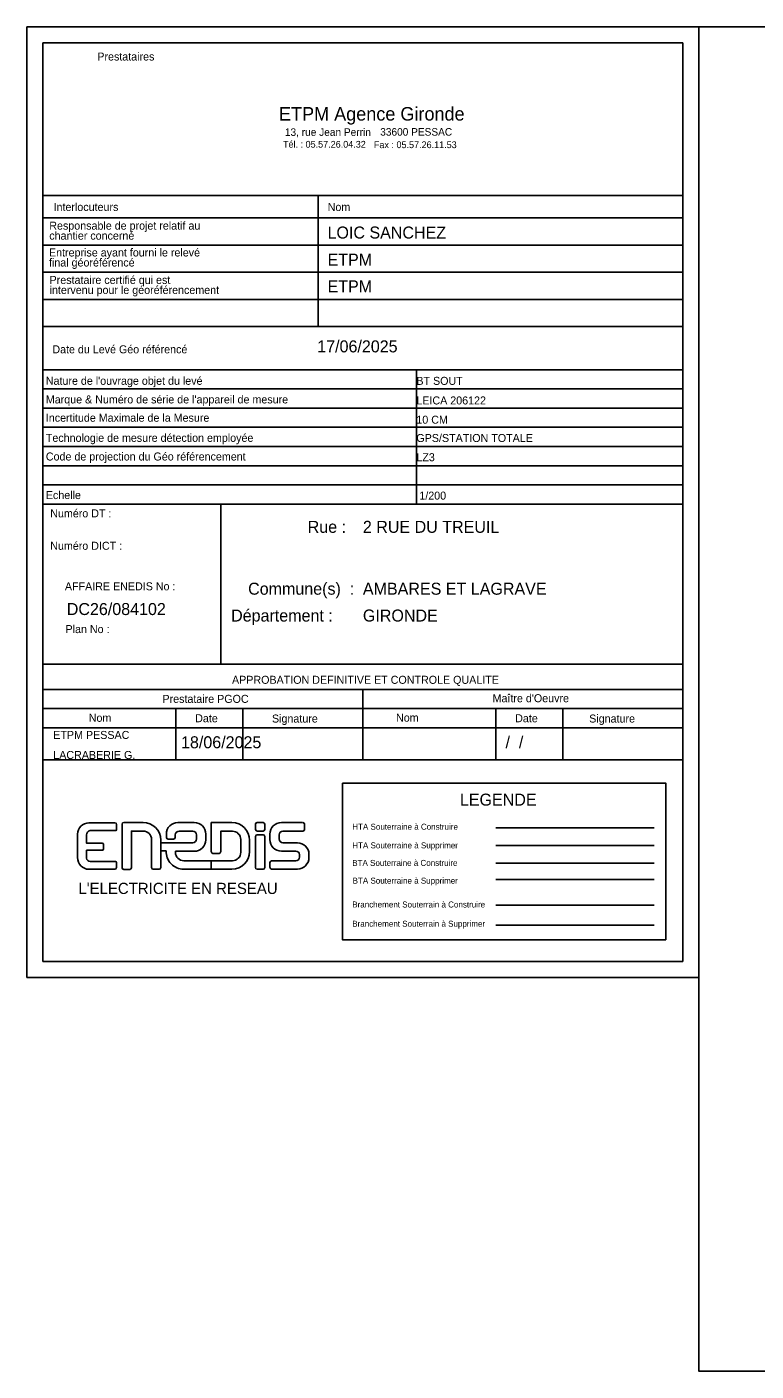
# Model space of a CAD drawing. Extents: x 376946 to 377047, y 296637 to 296721.
# Drawn here: x 376945.7 to 376991.3, y 296637.1 to 296721.1 of the extents above; entities that cross this region are included whole.
import ezdxf

# ---------------------------------------------------------------- set-up
doc = ezdxf.new("R2010")
doc.units = 0
for name, color, linetype in [('Cartouche', 7, 'Continuous'), ('CellulesEchanges', 7, 'Continuous'), ('Limites et Hydro', 7, 'Continuous'), ('PGOC_HABILLAGE_PGOC', 7, 'Continuous'), ('Texte libre', 7, 'Continuous')]:
    doc.layers.add(name, color=color, linetype=linetype)

msp = doc.modelspace()

# ---------------------------------------------------------------- linework, layer by layer
at = {"layer": 'Limites et Hydro'}
for p, q in [((376949.572, 296671.373), (376951.196, 296671.374)), ((376951.301, 296671.269), (376951.301, 296670.953)), ((376951.637, 296668.561), (376951.636, 296671.29)), ((376951.741, 296671.395), (376952.952, 296671.395)), ((376955.126, 296671.387), (376956.154, 296671.387)), ((376959.98, 296670.963), (376959.979, 296671.28)), ((376960.084, 296671.385), (376960.451, 296671.385)), ((376960.556, 296671.28), (376960.555, 296670.963)), ((376961.6, 296671.388), (376962.921, 296671.388)), ((376963.043, 296671.283), (376963.042, 296670.961)), ((376948.858, 296669.196), (376948.855, 296670.655)), ((376951.213, 296670.885), (376949.646, 296670.885)), ((376954.407, 296670.462), (376954.409, 296670.67)), ((376954.967, 296670.619), (376954.967, 296670.462)), ((376956.054, 296670.856), (376955.211, 296670.856)), ((376956.299, 296670.37), (376956.299, 296670.611)), ((376956.872, 296670.67), (376956.869, 296670.313)), ((376959.979, 296668.57), (376959.98, 296670.52)), ((376960.45, 296670.858), (376960.085, 296670.858)), ((376960.085, 296670.625), (376960.448, 296670.625)), ((376960.553, 296670.52), (376960.553, 296668.57)), ((376960.881, 296670.323), (376960.882, 296670.67)), ((376961.452, 296670.611), (376961.451, 296670.366)), ((376962.937, 296670.856), (376961.697, 296670.856)), ((376950.479, 296670.024), (376950.477, 296669.728)), ((376953.481, 296668.569), (376953.479, 296670.327)), ((376954.055, 296670.292), (376954.053, 296668.569)), ((376954.862, 296670.357), (376954.512, 296670.357)), ((376959.059, 296670.32), (376959.059, 296669.526)), ((376959.61, 296669.579), (376959.611, 296670.282)), ((376962.492, 296669.605), (376961.599, 296669.605)), ((376961.696, 296670.121), (376962.601, 296670.121)), ((376949.65, 296668.951), (376951.161, 296668.95)), ((376951.161, 296668.95), (376951.245, 296668.952)), ((376951.291, 296668.9), (376951.288, 296668.572)), ((376957.321, 296669.463), (376957.699, 296669.463)), ((376960.882, 296668.594), (376960.882, 296668.884)), ((376960.987, 296668.989), (376962.492, 296668.989)), ((376962.737, 296669.234), (376962.736, 296669.382)), ((376963.318, 296669.404), (376963.318, 296669.199)), ((376951.183, 296668.467), (376949.562, 296668.467)), ((376952.118, 296668.456), (376951.742, 296668.456)), ((376953.948, 296668.464), (376953.586, 296668.464)), ((376960.448, 296668.465), (376960.084, 296668.465)), ((376962.601, 296668.482), (376960.986, 296668.482))]:
    msp.add_line(p, q, dxfattribs=at)
for points in [[(376958.508, 296671.384), (376957.216, 296671.384), (376957.216, 296669.568)], [(376949.415, 296670.613), (376949.413, 296670.108), (376950.388, 296670.109)], [(376952.954, 296670.852), (376952.222, 296670.852), (376952.223, 296668.561)], [(376957.804, 296669.568), (376957.804, 296670.845), (376958.534, 296670.845)], [(376950.372, 296669.659), (376949.42, 296669.659), (376949.42, 296669.166)], [(376954.393, 296669.61), (376954.053, 296669.61), (376954.053, 296670.125), (376956.054, 296670.125)], [(376956.143, 296669.596), (376954.979, 296669.596), (376954.978, 296669.526)], [(376955.503, 296669.001), (376957.215, 296669.001), (376957.215, 296668.476), (376955.495, 296668.476)], [(376958.534, 296669.001), (376957.215, 296669.001), (376957.215, 296668.476), (376958.507, 296668.476)]]:
    msp.add_lwpolyline(points, dxfattribs=at)
for centre, radius, start, end in [((376949.572, 296670.655), 0.718, 90, 180), ((376951.196, 296671.269), 0.105, 0, 90), ((376951.741, 296671.29), 0.105, 90, 180), ((376952.952, 296670.292), 1.103, 0, 90), ((376955.126, 296670.67), 0.718, 90, 180), ((376956.154, 296670.67), 0.718, 0, 90), ((376958.508, 296670.282), 1.103, 0, 90), ((376960.084, 296671.28), 0.105, 90, 180), ((376960.451, 296671.28), 0.105, 0, 90), ((376961.6, 296670.67), 0.718, 90, 180), ((376962.938, 296671.283), 0.105, 0, 90), ((376949.666, 296670.633), 0.252, 94.58556, 184.58556), ((376951.223, 296670.962), 0.0783, 262.85047, 352.85047), ((376952.954, 296670.327), 0.525, 0, 90), ((376954.512, 296670.462), 0.105, 180, 270), ((376954.862, 296670.462), 0.105, 270, 0), ((376955.211, 296670.611), 0.245, 90, 178.0977), ((376956.054, 296670.611), 0.245, 0, 90), ((376956.054, 296670.37), 0.245, 270, 0), ((376958.534, 296670.32), 0.525, 0, 90), ((376960.085, 296670.963), 0.105, 180, 270), ((376960.085, 296670.52), 0.105, 90, 180), ((376960.448, 296670.52), 0.105, 0, 90), ((376960.45, 296670.963), 0.105, 270, 0), ((376961.696, 296670.366), 0.245, 180, 270), ((376961.697, 296670.611), 0.245, 90, 180), ((376962.937, 296670.961), 0.105, 270, 0), ((376950.39, 296669.746), 0.0886, 258.1056, 348.1056), ((376950.391, 296670.021), 0.0876, 1.9332, 91.9332), ((376955.495, 296669.579), 1.103, 178.39671, 270), ((376955.503, 296669.526), 0.525, 180, 270), ((376956.152, 296670.313), 0.718, 269.3345, 0), ((376957.321, 296669.568), 0.105, 180, 270), ((376957.699, 296669.568), 0.105, 270, 0), ((376958.507, 296669.579), 1.103, 270, 0), ((376958.534, 296669.526), 0.525, 270, 0), ((376961.599, 296670.323), 0.718, 180, 270), ((376962.492, 296669.36), 0.245, 5.13494, 90), ((376962.601, 296669.404), 0.718, 0, 90), ((376949.574, 296669.183), 0.716, 179.02797, 269.02797), ((376949.643, 296669.173), 0.223, 181.91632, 271.91632), ((376951.242, 296668.903), 0.0489, 356.13303, 86.13303), ((376960.987, 296668.884), 0.105, 90, 180), ((376962.492, 296669.234), 0.245, 270, 0), ((376962.601, 296669.199), 0.718, 270, 0), ((376951.183, 296668.572), 0.105, 270, 0), ((376951.742, 296668.561), 0.105, 180, 270), ((376952.118, 296668.561), 0.105, 270, 0), ((376953.586, 296668.569), 0.105, 180, 270), ((376953.948, 296668.569), 0.105, 270, 0), ((376960.084, 296668.57), 0.105, 180, 270), ((376960.448, 296668.57), 0.105, 270, 0), ((376960.986, 296668.587), 0.105, 175.77322, 270)]:
    msp.add_arc(centre, radius, start, end, dxfattribs=at)
at = {"layer": 'PGOC_HABILLAGE_PGOC'}
for p, q in [((376986.689, 296720.108), (376946.689, 296720.108)), ((376946.689, 296720.108), (376946.689, 296662.708)), ((376986.689, 296662.708), (376986.689, 296720.108)), ((376946.689, 296710.574), (376986.689, 296710.574)), ((376946.689, 296709.174), (376986.689, 296709.174)), ((376946.689, 296707.477), (376986.689, 296707.477)), ((376946.689, 296705.777), (376986.689, 296705.777)), ((376946.689, 296704.077), (376986.689, 296704.077)), ((376946.689, 296702.377), (376986.689, 296702.377)), ((376946.689, 296699.684), (376986.689, 296699.684)), ((376970.035, 296699.684), (376970.035, 296691.284)), ((376946.689, 296698.484), (376986.689, 296698.484)), ((376946.689, 296697.284), (376986.689, 296697.284)), ((376946.689, 296696.084), (376986.689, 296696.084)), ((376946.689, 296694.884), (376986.689, 296694.884)), ((376946.689, 296693.684), (376986.689, 296693.684)), ((376946.689, 296692.484), (376986.689, 296692.484)), ((376946.689, 296691.284), (376986.689, 296691.284)), ((376946.689, 296691.284), (376986.689, 296691.284)), ((376957.819, 296691.284), (376957.819, 296681.284)), ((376946.689, 296681.284), (376986.689, 296681.284)), ((376946.689, 296679.708), (376986.689, 296679.708)), ((376966.689, 296679.708), (376966.689, 296675.308)), ((376946.689, 296678.508), (376986.689, 296678.508)), ((376954.991, 296678.508), (376954.991, 296675.308)), ((376959.196, 296678.508), (376959.196, 296675.308)), ((376974.991, 296678.508), (376974.991, 296675.308)), ((376979.196, 296678.508), (376979.196, 296675.308)), ((376946.689, 296677.308), (376986.689, 296677.308)), ((376946.689, 296675.308), (376986.689, 296675.308)), ((376946.689, 296662.708), (376986.689, 296662.708))]:
    msp.add_line(p, q, dxfattribs=at)
for points in [[(376945.689, 296721.108), (376987.689, 296721.108), (376987.689, 296661.708), (376945.689, 296661.708)], [(376987.689, 296721.108), (376987.689, 296637.108), (377047.089, 296637.108), (377047.089, 296721.108)]]:
    msp.add_lwpolyline(points, close=True, dxfattribs=at)
for points in [[(376963.899, 296710.574), (376963.899, 296702.377)], [(376965.419, 296673.855), (376965.419, 296664.053), (376985.623, 296664.053)], [(376985.623, 296664.053), (376985.623, 296673.855), (376965.419, 296673.855)]]:
    msp.add_lwpolyline(points, dxfattribs=at)
at = {"layer": 'Texte libre'}
for points in [[(376974.991, 296671.054), (376984.896, 296671.054)], [(376974.991, 296669.95), (376984.896, 296669.95)], [(376974.991, 296668.85), (376984.896, 296668.85)], [(376974.991, 296667.821), (376984.896, 296667.821)], [(376974.991, 296666.231), (376984.896, 296666.231)], [(376974.991, 296664.977), (376984.896, 296664.977)]]:
    msp.add_lwpolyline(points, dxfattribs=at)

# ---------------------------------------------------------------- texts
at = {"layer": 'Cartouche'}
for s, height, p in [('ETPM Agence Gironde', 0.84375, (376961.448, 296715.253)), ('13, rue Jean Perrin', 0.4725, (376961.817, 296714.295)), ('33600 PESSAC', 0.4725, (376967.775, 296714.311)), ('Tél. : 05.57.26.04.32', 0.42187, (376961.698, 296713.561)), ('Fax : 05.57.26.11.53', 0.42187, (376967.38, 296713.531))]:
    msp.add_text(s, height=height, dxfattribs=at).set_placement(p)
at = {"layer": 'CellulesEchanges'}
for s, height, p in [('LOIC SANCHEZ', 0.75, (376964.481, 296707.882)), ('ETPM', 0.75, (376964.481, 296706.185)), ('ETPM', 0.75, (376964.481, 296704.518)), ('17/06/2025', 0.75, (376963.84, 296700.768)), ('BT SOUT', 0.5, (376970.035, 296698.738)), ('LEICA 206122', 0.5, (376970.035, 296697.514)), ('10 CM', 0.5, (376970.035, 296696.311)), ('GPS/STATION TOTALE', 0.5, (376970.035, 296695.167)), ('LZ3', 0.5, (376970.035, 296693.967)), (' 1/200', 0.5, (376970.035, 296691.567)), ('2 RUE DU TREUIL', 0.75, (376966.691, 296689.491)), ('AMBARES ET LAGRAVE', 0.75, (376966.691, 296685.625)), ('DC26/084102', 0.75, (376948.184, 296684.354)), ('GIRONDE', 0.75, (376966.691, 296683.948)), ('ETPM PESSAC', 0.5, (376947.339, 296676.612)), ('18/06/2025', 0.75, (376955.325, 296676.029)), ('   /  /    ', 0.75, (376974.77, 296676.029)), ('LACRABERIE G.', 0.5, (376947.339, 296675.36))]:
    msp.add_text(s, height=height, dxfattribs=at).set_placement(p)
at = {"layer": 'Limites et Hydro'}
msp.add_text("L'ELECTRICITE EN RESEAU", height=0.7, dxfattribs=at).set_placement((376948.91, 296666.923))
at = {"layer": 'PGOC_HABILLAGE_PGOC'}
for s, height, p in [('Prestataires', 0.5, (376950.092, 296719.005)), ('Interlocuteurs', 0.5, (376947.357, 296709.604)), ('Nom', 0.5, (376964.491, 296709.604)), ('chantier concerné', 0.5, (376947.09, 296707.812)), ('Responsable de projet relatif au', 0.5, (376947.09, 296708.438)), ('final géoréférencé', 0.5, (376947.071, 296706.134)), ('Entreprise ayant fourni le relevé', 0.5, (376947.071, 296706.76)), ('intervenu pour le géoréférencement', 0.5, (376947.11, 296704.418)), ('Prestataire certifié qui est', 0.5, (376947.11, 296705.044)), ('Date du Levé Géo référencé', 0.5, (376947.282, 296700.71)), (" Nature de l'ouvrage objet du levé", 0.5, (376946.689, 296698.742)), (" Marque & Numéro de série de l'appareil de mesure", 0.5, (376946.689, 296697.578)), (' Incertitude Maximale de la Mesure', 0.5, (376946.689, 296696.434)), (' Technologie de mesure détection employée', 0.5, (376946.689, 296695.177)), (' Code de projection du Géo référencement', 0.5, (376946.689, 296694.011)), (' Echelle', 0.5, (376946.689, 296691.601)), ('Numéro DT :', 0.5, (376947.149, 296690.458)), ('Rue :   ', 0.75, (376963.241, 296689.491)), ('Numéro DICT :', 0.5, (376947.149, 296688.433)), ('AFFAIRE ENEDIS No :', 0.5, (376948.066, 296685.9)), ('Commune(s)  :   ', 0.75, (376959.518, 296685.625)), ('Département :   ', 0.75, (376958.455, 296683.948)), ('Plan No :', 0.5, (376948.105, 296683.226)), ('APPROBATION DEFINITIVE ET CONTROLE QUALITE', 0.5, (376958.511, 296680.057)), ('Prestataire PGOC', 0.5, (376954.163, 296678.866)), ("Maître d'Oeuvre", 0.5, (376974.8, 296678.906)), ('Nom', 0.5, (376949.556, 296677.683)), ('Date', 0.5, (376956.21, 296677.655)), ('Signature', 0.5, (376961.009, 296677.636)), ('Nom', 0.5, (376968.764, 296677.693)), ('Date', 0.5, (376976.21, 296677.655)), ('Signature', 0.5, (376980.837, 296677.636)), ('LEGENDE   ', 0.75, (376972.755, 296672.444)), ('HTA Souterraine à Construire', 0.375, (376966.027, 296670.938)), ('HTA Souterraine à Supprimer', 0.375, (376966.027, 296669.773)), ('BTA Souterraine à Construire', 0.375, (376966.027, 296668.678)), ('BTA Souterraine à Supprimer', 0.375, (376966.05, 296667.569)), ('Branchement Souterrain à Construire', 0.375, (376966.027, 296666.079)), ('Branchement Souterrain à Supprimer', 0.375, (376966.027, 296664.877))]:
    msp.add_text(s, height=height, dxfattribs=at).set_placement(p)

doc.saveas('drawing.dxf')
